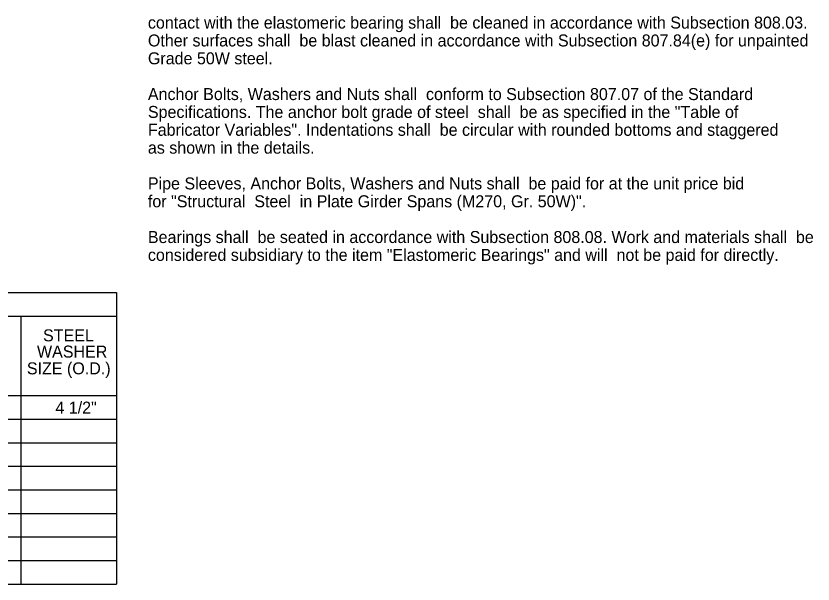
# Model space of a CAD drawing. Extents: x -194 to 226, y 505 to 725.
# Drawn here: x 47.6 to 130.7, y 542.1 to 601.3 of the extents above; entities that cross this region are included whole.
import ezdxf

# ---------------------------------------------------------------- set-up
doc = ezdxf.new("R2010")
doc.units = 0
doc.layers.add('Level 40', color=7, linetype='Continuous')
doc.layers.add('Level 41', color=7, linetype='Continuous')

msp = doc.modelspace()

# ---------------------------------------------------------------- linework, layer by layer
at = {"layer": 'Level 40'}
for p, q in [((48.111, 570.011), (48.111, 542.092)), ((-173.559, 561.719), (58.082, 561.719)), ((48.111, 562.218), (48.111, 558.728)), ((-173.559, 559.266), (58.082, 559.266)), ((-173.559, 556.812), (58.082, 556.812)), ((-173.559, 556.812), (58.082, 556.812)), ((-173.559, 554.359), (58.082, 554.359)), ((-173.559, 554.359), (58.082, 554.359)), ((-173.559, 551.906), (58.082, 551.906)), ((-173.559, 551.905), (58.082, 551.905)), ((-173.559, 549.452), (58.082, 549.452)), ((-173.559, 546.999), (58.082, 546.999)), ((-173.559, 544.545), (58.082, 544.545))]:
    msp.add_line(p, q, dxfattribs=at)
at = {"layer": 'Level 41'}
for p, q in [((-92.484, 572.464), (58.082, 572.464)), ((58.082, 572.464), (58.082, 542.092)), ((-173.559, 570.011), (58.082, 570.011)), ((-173.559, 542.092), (58.082, 542.092))]:
    msp.add_line(p, q, dxfattribs=at)

# ---------------------------------------------------------------- texts
at = {"layer": 'Level 40'}
for s, p in [('contact with the elastomeric bearing shall  be cleaned in accordance with Subsection 808.03.', (61.341, 599.956)), ('Other surfaces shall  be blast cleaned in accordance with Subsection 807.84(e) for unpainted', (61.341, 598.094)), ('Grade 50W steel.', (61.341, 596.233)), ('Anchor Bolts, Washers and Nuts shall  conform to Subsection 807.07 of the Standard', (61.341, 592.51)), ('Specifications. The anchor bolt grade of steel  shall  be as specified in the "Table of', (61.341, 590.648)), ('Fabricator Variables". Indentations shall  be circular with rounded bottoms and staggered', (61.341, 588.787)), ('as shown in the details.', (61.341, 586.925)), ('Pipe Sleeves, Anchor Bolts, Washers and Nuts shall  be paid for at the unit price bid', (61.341, 583.202)), ('for "Structural  Steel  in Plate Girder Spans (M270, Gr. 50W)".', (61.341, 581.34)), ('Bearings shall  be seated in accordance with Subsection 808.08. Work and materials shall  be', (61.341, 577.617)), ('considered subsidiary to the item "Elastomeric Bearings" and will  not be paid for directly.', (61.341, 575.756)), ('STEEL', (50.41, 567.375)), ('WASHER', (49.777, 565.682)), ('SIZE (O.D.)', (48.725, 563.937)), ('4 1/2"', (51.701, 559.846))]:
    msp.add_text(s, height=1.25, dxfattribs=at).set_placement(p)

doc.saveas('drawing.dxf')
